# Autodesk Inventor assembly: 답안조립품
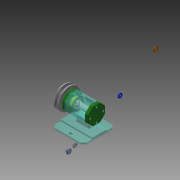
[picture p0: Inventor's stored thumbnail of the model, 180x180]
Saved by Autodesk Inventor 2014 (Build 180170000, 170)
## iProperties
Created: 2018-06
Part Number: 답안조립품
Document SubType Name: Assembly
Designer: kh
Author: kh
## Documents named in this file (16)
- C:\Users\kh\Desktop\480607V1022\답안조립품.iam
- C:\Users\kh\Desktop\480607V1022\본체.ipt
- C:\Users\kh\Desktop\480607V1022\V벨트풀리.ipt
- C:\Users\kh\Desktop\480607V1022\고무캡.ipt
- C:\Users\kh\Desktop\480607V1022\너트 M8.ipt
- 너트 M8.ipt
- C:\Users\kh\Desktop\480607V1022\뒤커버.ipt
- C:\Users\kh\Desktop\480607V1022\베어링 15x32x9.ipt
- C:\Users\kh\Desktop\480607V1022\볼트 M4x12.ipt
- C:\Users\kh\Desktop\480607V1022\스프링와셔 8.ipt
- C:\Users\kh\Desktop\480607V1022\앞커버.ipt
- C:\Users\kh\Desktop\480607V1022\오일 실 15 25 7.ipt
- C:\Users\kh\Desktop\480607V1022\와셔 8x17.ipt
- C:\Users\kh\Desktop\480607V1022\축.ipt
- C:\Users\kh\Desktop\480607V1022\키 3x3x12.ipt
- 키 3x3x12.ipt
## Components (2 placed, 2 different names)
1. V벨트풀리:1 — Insert:9, Mate:5, Mate:6
2. 고무캡:1
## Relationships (3: Mate 2, Insert 1)
- Insert:9: V벨트풀리:1
- Mate:5: V벨트풀리:1
- Mate:6: V벨트풀리:1
